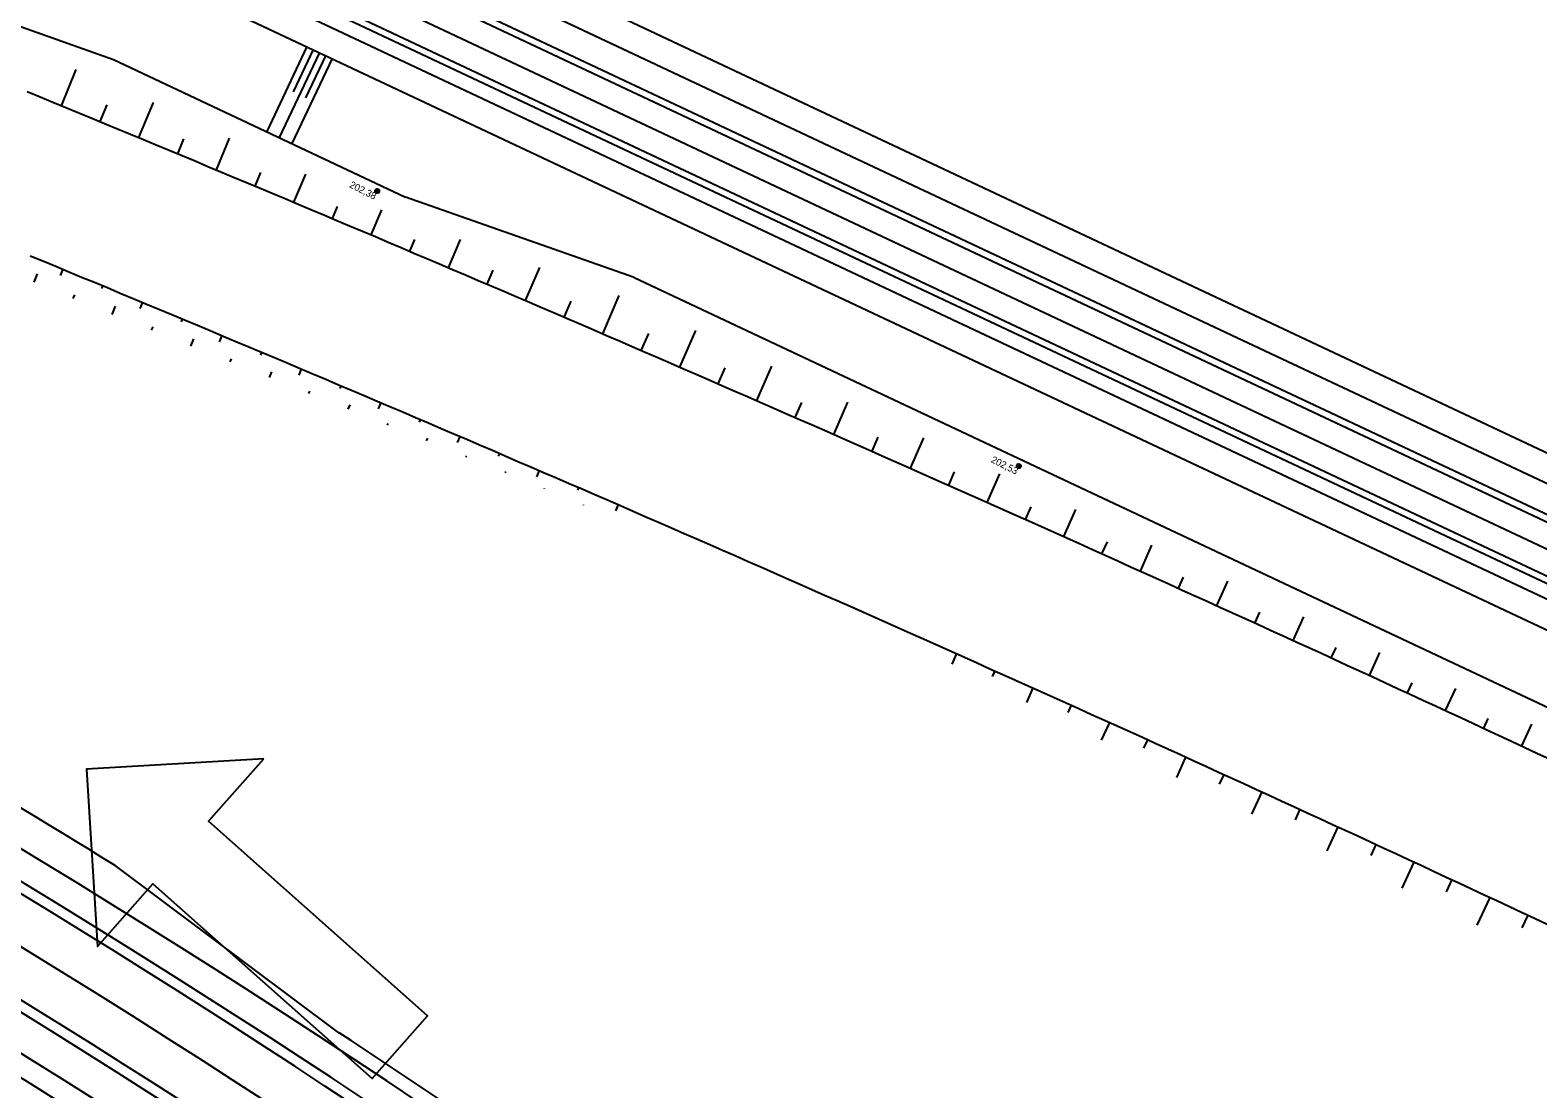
# Model space of a CAD drawing. Extents: x -552278 to -547230, y -1151007 to -1148251.
# Drawn here: x -550664.2 to -550556.1, y -1148912.8 to -1148836.9 of the extents above; entities that cross this region are included whole.
import ezdxf

# ---------------------------------------------------------------- set-up
doc = ezdxf.new("R2010")
doc.units = 0
for name, color, linetype in [('prijezdy', 7, 'Continuous'), ('SO221815_VYSKOPIS', 7, 'Continuous'), ('u_trat navrh', 7, 'Continuous')]:
    doc.layers.add(name, color=color, linetype=linetype)

# ---------------------------------------------------------------- blocks, each defined once
blk = doc.blocks.new('SO221824_VYSKOPIS')
at = {"layer": 'SO221815_VYSKOPIS'}
for p, q in [((1.2, -0.9), (-1.2, 0.9)), ((0.9, 1.2), (-0.9, -1.2)), ((0.9, 1.2), (0, 0)), ((0, 0), (1.2, -0.9))]:
    blk.add_line(p, q, dxfattribs=at)
blk.add_lwpolyline([(-0.9, -1.2), (0, 0), (-1.2, 0.9)], dxfattribs=at)
blk.add_circle((0, 0), 1.5, dxfattribs=at)
for start, end in [(145.362, 235.1538), (325.362, 55.1538)]:
    blk.add_arc((0, 0), 1.5, start, end, dxfattribs=at)

msp = doc.modelspace()

# ---------------------------------------------------------------- linework, layer by layer
at = {"layer": 'prijezdy'}
msp.add_lwpolyline([(-550647.44, -1148889.13), (-550660.15, -1148889.89), (-550659.38, -1148902.6), (-550655.4, -1148898.11), (-550639.69, -1148912.04), (-550635.71, -1148907.55), (-550651.42, -1148893.62), (-550647.44, -1148889.13)], dxfattribs=at)
at = {"layer": 'u_trat navrh'}
for p, q in [((-550646.64, -1148824.31), (-550514.41, -1148886.51)), ((-550647.49, -1148826.12), (-550515.26, -1148888.32)), ((-550648.34, -1148827.93), (-550516.12, -1148890.13)), ((-550648.55, -1148828.38), (-550516.33, -1148890.59)), ((-550649.3, -1148829.97), (-550517.07, -1148892.17)), ((-550681.03, -1148830.96), (-550658.23, -1148839.02)), ((-550650.04, -1148831.55), (-550517.82, -1148893.75)), ((-550650.68, -1148832.91), (-550518.46, -1148895.11)), ((-550651.53, -1148834.72), (-550519.31, -1148896.92)), ((-550658.23, -1148839.02), (-550637.29, -1148848.88)), ((-550644.37, -1148838.09), (-550647.24, -1148844.19)), ((-550643.46, -1148838.51), (-550646.34, -1148844.62)), ((-550642.56, -1148838.94), (-550645.43, -1148845.05)), ((-550643.92, -1148838.3), (-550645.35, -1148841.35)), ((-550643.01, -1148838.72), (-550644.45, -1148841.78)), ((-550661.96, -1148842.33), (-550660.89, -1148839.74)), ((-550659.18, -1148843.47), (-550658.68, -1148842.28)), ((-550656.4, -1148844.62), (-550655.35, -1148842.1)), ((-550653.62, -1148845.78), (-550653.17, -1148844.7)), ((-550650.84, -1148846.93), (-550649.9, -1148844.67)), ((-550648.07, -1148848.09), (-550647.66, -1148847.13)), ((-550645.29, -1148849.25), (-550644.44, -1148847.23)), ((-550642.52, -1148850.42), (-550642.16, -1148849.56)), ((-550639.75, -1148851.59), (-550638.99, -1148849.8)), ((-550620.9, -1148854.65), (-550637.29, -1148848.88)), ((-550636.98, -1148852.76), (-550636.63, -1148851.93)), ((-550634.21, -1148853.94), (-550633.35, -1148851.92)), ((-550661.85, -1148854.05), (-550662.04, -1148854.5)), ((-550631.44, -1148855.12), (-550631.02, -1148854.13)), ((-550628.68, -1148856.3), (-550627.66, -1148853.92)), ((-550663.91, -1148854.97), (-550663.67, -1148854.39)), ((-550659, -1148855.24), (-550659.08, -1148855.44)), ((-550620.9, -1148854.65), (-550521.44, -1148901.44)), ((-550661.11, -1148856.15), (-550661, -1148855.88)), ((-550656.15, -1148856.42), (-550656.34, -1148856.87)), ((-550625.91, -1148857.49), (-550625.42, -1148856.34)), ((-550623.15, -1148858.68), (-550621.97, -1148855.93)), ((-550658.31, -1148857.3), (-550658.07, -1148856.71)), ((-550655.49, -1148858.43), (-550655.39, -1148858.18)), ((-550653.3, -1148857.61), (-550653.38, -1148857.81)), ((-550617.63, -1148861.07), (-550616.49, -1148858.45)), ((-550652.67, -1148859.56), (-550652.47, -1148859.05)), ((-550650.45, -1148858.8), (-550650.64, -1148859.25)), ((-550620.39, -1148859.87), (-550619.86, -1148858.65)), ((-550649.85, -1148860.68), (-550649.77, -1148860.47)), ((-550647.61, -1148860), (-550647.69, -1148860.2)), ((-550647.03, -1148861.81), (-550646.87, -1148861.4)), ((-550644.76, -1148861.2), (-550644.95, -1148861.65)), ((-550614.87, -1148862.27), (-550614.37, -1148861.13)), ((-550612.11, -1148863.47), (-550611.04, -1148861.01)), ((-550644.22, -1148862.95), (-550644.15, -1148862.78)), ((-550641.92, -1148862.4), (-550642, -1148862.6)), ((-550641.41, -1148864.09), (-550641.27, -1148863.77)), ((-550639.07, -1148863.61), (-550639.26, -1148864.06)), ((-550609.36, -1148864.68), (-550608.89, -1148863.61)), ((-550606.6, -1148865.89), (-550605.59, -1148863.58)), ((-550636.23, -1148864.82), (-550636.32, -1148865.02)), ((-550638.59, -1148865.22), (-550638.54, -1148865.1)), ((-550635.78, -1148866.36), (-550635.69, -1148866.15)), ((-550633.39, -1148866.03), (-550633.59, -1148866.48)), ((-550603.85, -1148867.1), (-550603.41, -1148866.09)), ((-550601.1, -1148868.31), (-550600.14, -1148866.14)), ((-550632.96, -1148867.5), (-550632.93, -1148867.43)), ((-550630.56, -1148867.25), (-550630.64, -1148867.45)), ((-550630.15, -1148868.63), (-550630.11, -1148868.54)), ((-550627.72, -1148868.47), (-550627.91, -1148868.92)), ((-550598.35, -1148869.53), (-550597.93, -1148868.58)), ((-550595.6, -1148870.76), (-550594.69, -1148868.71)), ((-550627.34, -1148869.8), (-550627.33, -1148869.77)), ((-550624.89, -1148869.69), (-550624.97, -1148869.89)), ((-550624.54, -1148870.97), (-550624.53, -1148870.94)), ((-550622.05, -1148870.92), (-550622.25, -1148871.37)), ((-550592.86, -1148871.98), (-550592.45, -1148871.09)), ((-550590.11, -1148873.21), (-550589.24, -1148871.27)), ((-550587.37, -1148874.44), (-550586.98, -1148873.59)), ((-550584.62, -1148875.68), (-550583.79, -1148873.83)), ((-550581.88, -1148876.92), (-550581.52, -1148876.11)), ((-550579.14, -1148878.16), (-550578.34, -1148876.4)), ((-550576.41, -1148879.41), (-550576.05, -1148878.63)), ((-550573.67, -1148880.66), (-550572.89, -1148878.96)), ((-550570.93, -1148881.91), (-550570.59, -1148881.16)), ((-550597.8, -1148881.6), (-550598.13, -1148882.35)), ((-550568.2, -1148883.16), (-550567.45, -1148881.52)), ((-550595.06, -1148882.83), (-550595.23, -1148883.23)), ((-550592.32, -1148884.06), (-550592.79, -1148885.1)), ((-550565.47, -1148884.42), (-550565.13, -1148883.69)), ((-550562.74, -1148885.68), (-550562, -1148884.09)), ((-550589.58, -1148885.29), (-550589.82, -1148885.83)), ((-550586.84, -1148886.53), (-550587.43, -1148887.81)), ((-550560.01, -1148886.95), (-550559.68, -1148886.24)), ((-550557.28, -1148888.22), (-550556.55, -1148886.65)), ((-550584.11, -1148887.77), (-550584.39, -1148888.38)), ((-550581.38, -1148889.01), (-550582.04, -1148890.47)), ((-550578.64, -1148890.26), (-550578.96, -1148890.96)), ((-550575.91, -1148891.51), (-550576.65, -1148893.1)), ((-550573.19, -1148892.76), (-550573.53, -1148893.51)), ((-550570.46, -1148894.01), (-550571.26, -1148895.74)), ((-550567.73, -1148895.27), (-550568.11, -1148896.08)), ((-550642.06, -1148908.77), (-550658.11, -1148896.78)), ((-550565.01, -1148896.54), (-550565.87, -1148898.4)), ((-550562.29, -1148897.8), (-550562.69, -1148898.67)), ((-550559.57, -1148899.07), (-550560.49, -1148901.06)), ((-550556.85, -1148900.34), (-550557.27, -1148901.25))]:
    msp.add_line(p, q, dxfattribs=at)
for points in [[(-550518.03, -1148894.2), (-550650.25, -1148832)], [(-550664.41, -1148841.32), (-550663.49, -1148841.7), (-550662.56, -1148842.08), (-550661.63, -1148842.46), (-550660.71, -1148842.84), (-550659.78, -1148843.22), (-550658.86, -1148843.6), (-550657.93, -1148843.99), (-550657.01, -1148844.37), (-550656.08, -1148844.75), (-550655.16, -1148845.14), (-550654.23, -1148845.52), (-550653.31, -1148845.91), (-550652.38, -1148846.29), (-550651.46, -1148846.68), (-550650.53, -1148847.06), (-550649.61, -1148847.45), (-550648.69, -1148847.83), (-550647.76, -1148848.22), (-550646.84, -1148848.61), (-550645.91, -1148848.99), (-550644.99, -1148849.38), (-550644.07, -1148849.77), (-550643.14, -1148850.16), (-550642.22, -1148850.55), (-550641.3, -1148850.94), (-550640.38, -1148851.32), (-550639.45, -1148851.71), (-550638.53, -1148852.11), (-550637.61, -1148852.5), (-550636.69, -1148852.89), (-550635.77, -1148853.28), (-550634.85, -1148853.67), (-550633.92, -1148854.06), (-550633, -1148854.45), (-550632.08, -1148854.85), (-550631.16, -1148855.24), (-550630.24, -1148855.63), (-550629.32, -1148856.03), (-550628.4, -1148856.42), (-550627.48, -1148856.82), (-550626.56, -1148857.21), (-550625.64, -1148857.61), (-550624.72, -1148858), (-550623.8, -1148858.4), (-550622.88, -1148858.8), (-550621.96, -1148859.19), (-550621.04, -1148859.59), (-550620.12, -1148859.99), (-550619.2, -1148860.38), (-550618.28, -1148860.78), (-550617.37, -1148861.18), (-550616.45, -1148861.58), (-550615.53, -1148861.98), (-550614.61, -1148862.38), (-550613.69, -1148862.78), (-550612.77, -1148863.18), (-550611.86, -1148863.58), (-550610.94, -1148863.98), (-550610.02, -1148864.38), (-550609.11, -1148864.79), (-550608.19, -1148865.19), (-550607.27, -1148865.59), (-550606.36, -1148865.99), (-550605.44, -1148866.4), (-550604.52, -1148866.8), (-550603.61, -1148867.21), (-550602.69, -1148867.61), (-550601.77, -1148868.02), (-550600.86, -1148868.42), (-550599.94, -1148868.83), (-550599.03, -1148869.23), (-550598.11, -1148869.64), (-550597.2, -1148870.05), (-550596.28, -1148870.45), (-550595.37, -1148870.86), (-550594.45, -1148871.27), (-550593.54, -1148871.68), (-550592.62, -1148872.09), (-550591.71, -1148872.49), (-550590.8, -1148872.9), (-550589.88, -1148873.31), (-550588.97, -1148873.72), (-550588.06, -1148874.13), (-550587.14, -1148874.54), (-550586.23, -1148874.96), (-550585.32, -1148875.37), (-550584.4, -1148875.78), (-550583.49, -1148876.19), (-550582.58, -1148876.6), (-550581.67, -1148877.02), (-550580.75, -1148877.43), (-550579.84, -1148877.84), (-550578.93, -1148878.26), (-550578.02, -1148878.67), (-550577.11, -1148879.09), (-550576.2, -1148879.5), (-550575.29, -1148879.92), (-550574.38, -1148880.33), (-550573.46, -1148880.75), (-550572.55, -1148881.17), (-550571.64, -1148881.58), (-550570.73, -1148882), (-550569.82, -1148882.42), (-550568.91, -1148882.84), (-550568, -1148883.25), (-550567.09, -1148883.67), (-550566.18, -1148884.09), (-550565.27, -1148884.51), (-550564.37, -1148884.93), (-550563.46, -1148885.35), (-550562.55, -1148885.77), (-550561.64, -1148886.19), (-550560.73, -1148886.61), (-550559.82, -1148887.04), (-550558.91, -1148887.46), (-550558.01, -1148887.88), (-550557.1, -1148888.3), (-550556.19, -1148888.73), (-550555.28, -1148889.15)], [(-550664.2, -1148853.08), (-550663.28, -1148853.46), (-550662.36, -1148853.84), (-550661.43, -1148854.23), (-550660.51, -1148854.61), (-550659.59, -1148854.99), (-550658.66, -1148855.37), (-550657.74, -1148855.76), (-550656.82, -1148856.14), (-550655.9, -1148856.52), (-550654.98, -1148856.91), (-550654.05, -1148857.29), (-550653.13, -1148857.68), (-550652.21, -1148858.06), (-550651.29, -1148858.45), (-550650.37, -1148858.84), (-550649.45, -1148859.22), (-550648.53, -1148859.61), (-550647.61, -1148860), (-550646.69, -1148860.38), (-550645.77, -1148860.77), (-550644.85, -1148861.16), (-550643.93, -1148861.55), (-550643.01, -1148861.94), (-550642.09, -1148862.33), (-550641.17, -1148862.72), (-550640.25, -1148863.11), (-550639.33, -1148863.5), (-550638.41, -1148863.89), (-550637.49, -1148864.28), (-550636.57, -1148864.67), (-550635.65, -1148865.06), (-550634.74, -1148865.46), (-550633.82, -1148865.85), (-550632.9, -1148866.24), (-550631.98, -1148866.64), (-550631.06, -1148867.03), (-550630.15, -1148867.42), (-550629.23, -1148867.82), (-550628.31, -1148868.21), (-550627.39, -1148868.61), (-550626.48, -1148869.01), (-550625.56, -1148869.4), (-550624.64, -1148869.8), (-550623.73, -1148870.19), (-550622.81, -1148870.59), (-550621.89, -1148870.99), (-550620.98, -1148871.39), (-550620.06, -1148871.79), (-550619.15, -1148872.18), (-550618.23, -1148872.58), (-550617.32, -1148872.98), (-550616.4, -1148873.38), (-550615.49, -1148873.78), (-550614.57, -1148874.18), (-550613.66, -1148874.58), (-550612.74, -1148874.99), (-550611.83, -1148875.39), (-550610.91, -1148875.79), (-550610, -1148876.19), (-550609.08, -1148876.59), (-550608.17, -1148877), (-550607.26, -1148877.4), (-550606.34, -1148877.8), (-550605.43, -1148878.21), (-550604.52, -1148878.61), (-550603.6, -1148879.02), (-550602.69, -1148879.42), (-550601.78, -1148879.83), (-550600.87, -1148880.23), (-550599.95, -1148880.64), (-550599.04, -1148881.05), (-550598.13, -1148881.45), (-550597.22, -1148881.86), (-550596.31, -1148882.27), (-550595.4, -1148882.68), (-550594.48, -1148883.09), (-550593.57, -1148883.5), (-550592.66, -1148883.9), (-550591.75, -1148884.31), (-550590.84, -1148884.72), (-550589.93, -1148885.13), (-550589.02, -1148885.54), (-550588.11, -1148885.96), (-550587.2, -1148886.37), (-550586.29, -1148886.78), (-550585.38, -1148887.19), (-550584.47, -1148887.6), (-550583.56, -1148888.02), (-550582.65, -1148888.43), (-550581.74, -1148888.84), (-550580.83, -1148889.26), (-550579.92, -1148889.67), (-550579.02, -1148890.09), (-550578.11, -1148890.5), (-550577.2, -1148890.92), (-550576.29, -1148891.33), (-550575.38, -1148891.75), (-550574.48, -1148892.17), (-550573.57, -1148892.58), (-550572.66, -1148893), (-550571.75, -1148893.42), (-550570.85, -1148893.84), (-550569.94, -1148894.25), (-550569.03, -1148894.67), (-550568.13, -1148895.09), (-550567.22, -1148895.51), (-550566.31, -1148895.93), (-550565.41, -1148896.35), (-550564.5, -1148896.77), (-550563.6, -1148897.19), (-550562.69, -1148897.61), (-550561.79, -1148898.03), (-550560.88, -1148898.46), (-550559.97, -1148898.88), (-550559.07, -1148899.3), (-550558.17, -1148899.72), (-550557.26, -1148900.15), (-550556.36, -1148900.57), (-550555.45, -1148901)]]:
    msp.add_lwpolyline(points, dxfattribs=at)
for radius, start, end in [(753.25, 51.79075, 76.89047), (754, 51.79075, 76.89047), (750, 47.42068, 76.89047), (746.75, 47.42068, 72.23343), (746, 47.42068, 72.23343), (756, 51.79075, 65.9476), (758.5, 58.30817, 60.98197), (743.5, 47.42068, 61.74591), (742, 47.42068, 61.3606), (757, 51.79075, 56.79736)]:
    msp.add_arc((-551056.59, -1149542.18), radius, start, end, dxfattribs=at)

# ---------------------------------------------------------------- block references
at = {"layer": 'u_trat navrh', "xscale": 0.1, "yscale": 0.09999999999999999, "rotation": -31.851985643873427}
for p in [(-550639.32, -1148848.45), (-550593.33, -1148868.15)]:
    msp.add_blockref('SO221824_VYSKOPIS', p, dxfattribs=at)

# ---------------------------------------------------------------- texts
at = {"layer": 'u_trat navrh'}
for s, p in [('202,38', (-550641.36, -1148848.16)), ('202,53', (-550595.37, -1148867.86))]:
    msp.add_text(s, height=0.5, rotation=333.2568, dxfattribs=at).set_placement(p)

doc.saveas('drawing.dxf')
